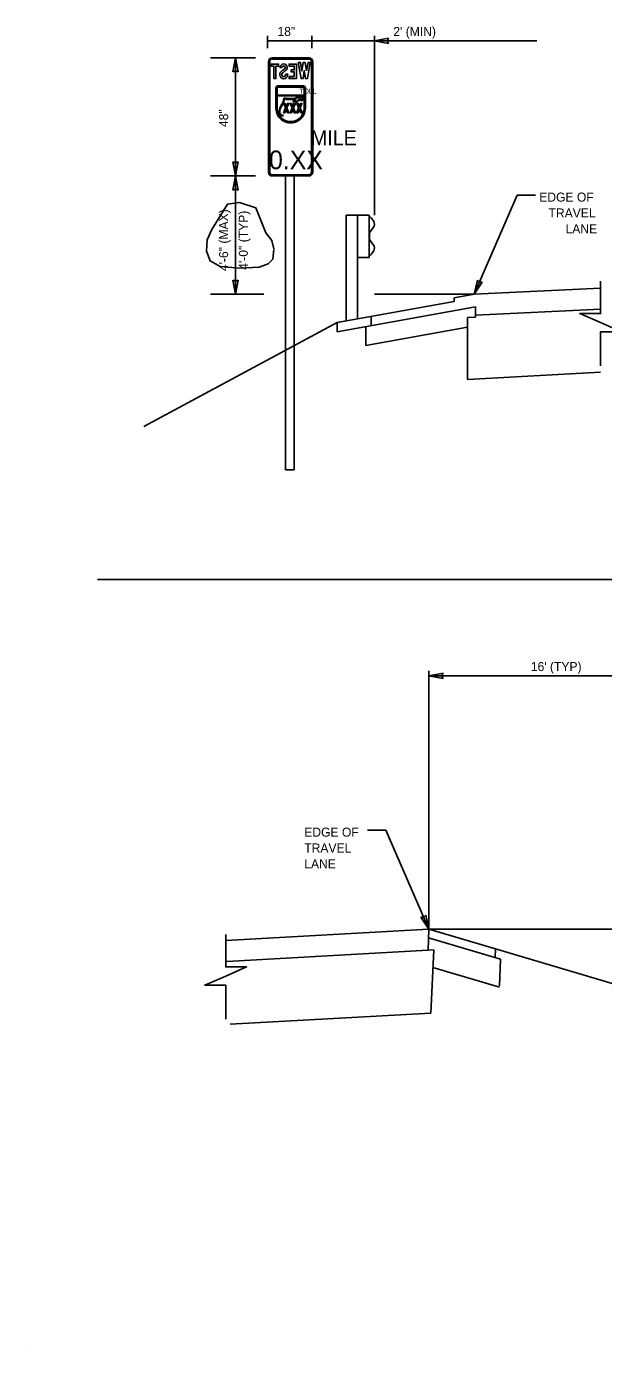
# Model space of a CAD drawing. Extents: x 56768 to 57406, y 11696 to 12105.
# Drawn here: x 56767.9 to 56946.4, y 11696.3 to 12105.2 of the extents above; entities that cross this region are included whole.
import ezdxf

# ---------------------------------------------------------------- set-up
doc = ezdxf.new("R2010")
doc.units = 0
for name, color, linetype in [('1', 7, 'Continuous'), ('52', 7, 'Continuous'), ('62', 7, 'Continuous'), ('AdhocPoint_dp', 7, 'Continuous'), ('Default', 7, 'Continuous'), ('DimLines_dp', 7, 'Continuous'), ('SheetBorder_dp', 7, 'Continuous'), ('SignPanel', 7, 'Continuous'), ('XSGrdLine_ex', 7, 'Continuous')]:
    doc.layers.add(name, color=color, linetype=linetype)

msp = doc.modelspace()

# ---------------------------------------------------------------- linework, layer by layer
at = {"layer": '1'}
for p, q in [((56848.03, 12005.09), (56848.03, 12058.97)), ((56850.69, 12006.52), (56850.69, 12058.97)), ((56848.03, 11968.2), (56848.03, 12005.09)), ((56850.69, 11968.2), (56850.69, 12006.52)), ((56850.69, 11968.2), (56848.03, 11968.2))]:
    msp.add_line(p, q, dxfattribs=at)
at = {"layer": '52'}
for p, q in [((56824.81, 12022.47), (56841.31, 12022.47)), ((56875.53, 12022.47), (56906.41, 12022.47)), ((56970.53, 11826.22), (56892.41, 11826.22))]:
    msp.add_line(p, q, dxfattribs=at)
at = {"layer": '62'}
msp.add_lwpolyline([(56844.47, 12036.41), (56843.77, 12039.01), (56841.97, 12041.42), (56838.86, 12049.17), (56833.76, 12050.77), (56830.06, 12050.27), (56825.26, 12042.42), (56823.76, 12039.21), (56823.56, 12035.71), (56824.76, 12032.7), (56827.86, 12031), (56833.76, 12030.5), (56839.86, 12030.8), (56842.67, 12031.8), (56844.07, 12033.31), (56844.47, 12036.21)], dxfattribs=at)
at = {"layer": 'AdhocPoint_dp'}
msp.add_line((56767.89, 11696.32), (56767.89, 11696.32), dxfattribs=at)
at = {"layer": 'Default'}
for points in [[(56945.5, 12000.28), (56945.5, 12010.84), (56951.96, 12010.84), (56945.5, 12013.65), (56939.04, 12016.47), (56945.5, 12016.47), (56945.5, 12026.47)], [(56829.53, 11798.37), (56829.53, 11808.93), (56823.07, 11808.93), (56829.53, 11811.74), (56835.99, 11814.56), (56829.53, 11814.56), (56829.53, 11824.56)]]:
    msp.add_lwpolyline(points, dxfattribs=at)
at = {"layer": 'DimLines_dp'}
for p, q in [((56842.51, 12098.47), (56842.51, 12102.3)), ((56856.2, 12098.47), (56856.2, 12102.3)), ((56875.53, 12046.89), (56875.53, 12102.3)), ((56856.2, 12100.75), (56842.51, 12100.75)), ((56856.2, 12100.75), (56925.74, 12100.75)), ((56875.53, 12100.75), (56879.88, 12101.59)), ((56879.88, 12099.94), (56875.53, 12100.75)), ((56879.88, 12101.59), (56879.55, 12100.75)), ((56879.55, 12100.75), (56879.88, 12099.94)), ((56824.81, 12095.47), (56838.74, 12095.47)), ((56831.74, 12091.12), (56832.55, 12095.47)), ((56832.55, 12095.47), (56832.55, 12058.97)), ((56832.55, 12095.47), (56833.39, 12091.12)), ((56832.55, 12091.45), (56831.74, 12091.12)), ((56833.39, 12091.12), (56832.55, 12091.45)), ((56832.55, 12058.97), (56831.71, 12063.32)), ((56831.71, 12063.32), (56832.55, 12062.99)), ((56832.55, 12058.97), (56831.71, 12063.32)), ((56831.71, 12063.32), (56832.55, 12062.99)), ((56832.55, 12062.99), (56833.36, 12063.32)), ((56833.36, 12063.32), (56832.55, 12058.97)), ((56832.55, 12062.99), (56833.36, 12063.32)), ((56833.36, 12063.32), (56832.55, 12058.97)), ((56824.81, 12058.97), (56838.74, 12058.97)), ((56831.74, 12054.62), (56832.55, 12058.97)), ((56832.55, 12058.97), (56832.55, 12022.47)), ((56832.55, 12058.97), (56833.39, 12054.62)), ((56832.55, 12054.95), (56831.74, 12054.62)), ((56833.39, 12054.62), (56832.55, 12054.95)), ((56919.73, 12053.08), (56906.41, 12022.46)), ((56925.38, 12053.08), (56919.73, 12053.08)), ((56832.55, 12022.47), (56831.71, 12026.82)), ((56831.71, 12026.82), (56832.55, 12026.49)), ((56832.55, 12026.49), (56833.36, 12026.82)), ((56833.36, 12026.82), (56832.55, 12022.47)), ((56906.41, 12022.46), (56907.37, 12026.79)), ((56908.89, 12026.13), (56906.41, 12022.46)), ((56907.37, 12026.79), (56908.01, 12026.15)), ((56908.01, 12026.15), (56908.89, 12026.13)), ((56892.41, 11826.22), (56892.41, 11906.05)), ((56896.76, 11905.31), (56892.41, 11904.5)), ((56892.41, 11904.5), (56896.76, 11903.66)), ((56973.53, 11904.5), (56892.41, 11904.5)), ((56896.43, 11904.5), (56896.76, 11905.31)), ((56896.76, 11903.66), (56896.43, 11904.5)), ((56873.44, 11856.84), (56879.09, 11856.84)), ((56879.09, 11856.84), (56892.41, 11826.22)), ((56890.8, 11829.91), (56889.93, 11829.89)), ((56889.93, 11829.89), (56892.41, 11826.22)), ((56891.44, 11830.55), (56890.8, 11829.91)), ((56892.41, 11826.22), (56891.44, 11830.55))]:
    msp.add_line(p, q, dxfattribs=at)
at = {"layer": 'SheetBorder_dp'}
msp.add_line((57405.89, 11934.25), (56789.89, 11934.25), dxfattribs=at)
at = {"layer": 'SignPanel'}
for p, q in [((56846.91, 12092.46), (56846.3, 12092.46)), ((56846.91, 12092.46), (56846.3, 12092.46)), ((56846.91, 12092.46), (56846.3, 12092.46)), ((56848.11, 12090.45), (56848.73, 12090.45)), ((56848.11, 12090.45), (56848.73, 12090.45)), ((56848.11, 12090.45), (56848.73, 12090.45)), ((56845.04, 12079.95), (56845.04, 12086.23)), ((56845.24, 12079.95), (56845.24, 12086.23)), ((56845.43, 12083.95), (56845.43, 12086.23)), ((56853.6, 12086.8), (56845.61, 12086.8)), ((56853.6, 12086.61), (56845.61, 12086.61)), ((56853.6, 12086.42), (56845.61, 12086.42)), ((56853.79, 12083.95), (56853.79, 12086.23)), ((56853.98, 12079.95), (56853.98, 12086.23)), ((56854.17, 12079.95), (56854.17, 12086.23)), ((56853.79, 12083.95), (56845.43, 12083.95)), ((56845.43, 12079.95), (56845.43, 12083.76)), ((56853.79, 12083.76), (56845.43, 12083.76)), ((56847.49, 12083.02), (56847.16, 12081.58)), ((56847.38, 12081.5), (56847.68, 12082.79)), ((56848.23, 12083.02), (56847.49, 12083.02)), ((56847.68, 12082.79), (56848.11, 12082.79)), ((56848.11, 12082.79), (56848.21, 12082.63)), ((56848.21, 12082.63), (56851.22, 12082.63)), ((56848.33, 12082.86), (56848.23, 12083.02)), ((56851.06, 12082.86), (56848.33, 12082.86)), ((56850.77, 12082.34), (56850.27, 12082)), ((56850.27, 12082), (56850.4, 12081.81)), ((56850.4, 12081.81), (56850.77, 12082.07)), ((56851.38, 12081.98), (56850.77, 12082.34)), ((56850.77, 12082.07), (56851.41, 12081.7)), ((56851.19, 12083.21), (56851.06, 12082.86)), ((56853.57, 12083.39), (56851.19, 12083.21)), ((56851.22, 12082.63), (56851.36, 12082.99)), ((56851.36, 12082.99), (56853.3, 12083.14)), ((56851.83, 12082.4), (56851.38, 12081.98)), ((56851.41, 12081.7), (56851.95, 12082.19)), ((56852.75, 12082.7), (56851.83, 12082.4)), ((56851.95, 12082.19), (56852.7, 12082.44)), ((56852.32, 12083.05), (56852.32, 12083.05)), ((56852.7, 12082.44), (56852.95, 12082.24)), ((56853.02, 12082.48), (56852.75, 12082.7)), ((56852.95, 12082.24), (56853.41, 12082.3)), ((56853.2, 12082.51), (56853.02, 12082.48)), ((56853.3, 12083.14), (56853.2, 12082.51)), ((56853.41, 12082.3), (56853.57, 12083.39)), ((56853.79, 12079.95), (56853.79, 12083.76)), ((56846.3, 12080), (56846.05, 12079.08)), ((56846.05, 12079.08), (56846.05, 12078.21)), ((56846.05, 12078.21), (56846.8, 12077.6)), ((56846.28, 12079.05), (56846.51, 12079.91)), ((56846.28, 12078.32), (56846.28, 12079.05)), ((56846.9, 12077.81), (56846.28, 12078.32)), ((56846.71, 12080.67), (56846.3, 12080)), ((56846.51, 12079.91), (56846.94, 12080.61)), ((56847.16, 12081.58), (56846.71, 12080.86)), ((56846.71, 12080.86), (56846.71, 12080.67)), ((56846.8, 12077.6), (56847.16, 12077.51)), ((56847.11, 12077.76), (56846.9, 12077.81)), ((56846.94, 12080.79), (56847.38, 12081.5)), ((56846.94, 12080.61), (56846.94, 12080.79)), ((56847.25, 12077.86), (56847.11, 12077.76)), ((56847.16, 12077.51), (56847.38, 12077.67)), ((56847.38, 12077.67), (56847.25, 12077.86))]:
    msp.add_line(p, q, dxfattribs=at)
for points in [[(56842.76, 12094.33), (56842.76, 12060.11)], [(56843.14, 12094.33), (56843.14, 12060.11)], [(56855.31, 12095.47), (56843.9, 12095.47)], [(56855.31, 12095.09), (56843.9, 12095.09)], [(56856.07, 12060.11), (56856.07, 12094.33)], [(56856.45, 12060.11), (56856.45, 12094.33)], [(56843.9, 12059.35), (56855.31, 12059.35)], [(56843.9, 12058.97), (56855.31, 12058.97)]]:
    msp.add_lwpolyline(points, dxfattribs=at)
for points in [[(56854.54, 12091.43), (56854.14, 12093.99), (56853.53, 12093.99), (56853.13, 12091.43), (56852.68, 12093.99), (56851.98, 12093.99), (56852.86, 12089.04), (56853.45, 12089.04), (56853.84, 12091.52), (56854.23, 12089.04), (56854.81, 12089.04), (56855.69, 12093.99), (56855, 12093.99)], [(56854.54, 12091.43), (56854.14, 12093.99), (56853.53, 12093.99), (56853.13, 12091.43), (56852.68, 12093.99), (56851.98, 12093.99), (56852.86, 12089.04), (56853.45, 12089.04), (56853.84, 12091.52), (56854.23, 12089.04), (56854.81, 12089.04), (56855.69, 12093.99), (56855, 12093.99)], [(56854.54, 12091.43), (56854.14, 12093.99), (56853.53, 12093.99), (56853.13, 12091.43), (56852.68, 12093.99), (56851.98, 12093.99), (56852.86, 12089.04), (56853.45, 12089.04), (56853.84, 12091.52), (56854.23, 12089.04), (56854.81, 12089.04), (56855.69, 12093.99), (56855, 12093.99)], [(56845.05, 12092.91), (56845.87, 12092.91), (56845.87, 12093.54), (56843.61, 12093.54), (56843.61, 12092.91), (56844.43, 12092.91), (56844.43, 12089.04), (56845.05, 12089.04)], [(56845.05, 12092.91), (56845.87, 12092.91), (56845.87, 12093.54), (56843.61, 12093.54), (56843.61, 12092.91), (56844.43, 12092.91), (56844.43, 12089.04), (56845.05, 12089.04)], [(56845.05, 12092.91), (56845.87, 12092.91), (56845.87, 12093.54), (56843.61, 12093.54), (56843.61, 12092.91), (56844.43, 12092.91), (56844.43, 12089.04), (56845.05, 12089.04)], [(56850.76, 12089.67), (56850.76, 12091.11), (56849.79, 12091.11), (56849.79, 12091.74), (56850.76, 12091.74), (56850.76, 12092.91), (56849.12, 12092.91), (56849.12, 12093.54), (56851.38, 12093.54), (56851.38, 12089.04), (56849.12, 12089.04), (56849.12, 12089.67)], [(56850.76, 12089.67), (56850.76, 12091.11), (56849.79, 12091.11), (56849.79, 12091.74), (56850.76, 12091.74), (56850.76, 12092.91), (56849.12, 12092.91), (56849.12, 12093.54), (56851.38, 12093.54), (56851.38, 12089.04), (56849.12, 12089.04), (56849.12, 12089.67)], [(56850.76, 12089.67), (56850.76, 12091.11), (56849.79, 12091.11), (56849.79, 12091.74), (56850.76, 12091.74), (56850.76, 12092.91), (56849.12, 12092.91), (56849.12, 12093.54), (56851.38, 12093.54), (56851.38, 12089.04), (56849.12, 12089.04), (56849.12, 12089.67)], [(56848.69, 12078.53), (56848.28, 12079.51), (56847.87, 12078.53), (56847.44, 12078.53), (56848.06, 12080.02), (56847.49, 12081.39), (56847.92, 12081.39), (56848.28, 12080.53), (56848.64, 12081.39), (56849.06, 12081.39), (56848.49, 12080.02), (56849.11, 12078.53)], [(56850.7, 12078.53), (56850.29, 12079.51), (56849.88, 12078.53), (56849.46, 12078.53), (56850.08, 12080.02), (56849.51, 12081.39), (56849.93, 12081.39), (56850.29, 12080.53), (56850.65, 12081.39), (56851.08, 12081.39), (56850.51, 12080.02), (56851.13, 12078.53)], [(56852.72, 12078.53), (56852.31, 12079.51), (56851.9, 12078.53), (56851.47, 12078.53), (56852.1, 12080.02), (56851.52, 12081.39), (56851.95, 12081.39), (56852.31, 12080.53), (56852.67, 12081.39), (56853.09, 12081.39), (56852.52, 12080.02), (56853.14, 12078.53)]]:
    msp.add_lwpolyline(points, close=True, dxfattribs=at)
for centre, radius, start, end in [((56843.9, 12094.33), 1.14, 90, 180), ((56843.9, 12094.33), 0.76, 90, 180), ((56855.31, 12094.33), 1.14, 0, 90), ((56855.31, 12094.33), 0.76, 0, 90), ((56843.9, 12060.11), 1.14, 180, 270), ((56843.9, 12060.11), 0.76, 180, 270), ((56855.31, 12060.11), 1.14, 270, 0), ((56855.31, 12060.11), 0.76, 270, 0)]:
    msp.add_arc(centre, radius, start, end, dxfattribs=at)
for centre, major_axis, ratio, start_param, end_param in [((56847.64, 12090.27), (0, -1.4), 0.981197, 3.939023, 5.163791), ((56847.64, 12090.27), (0, -1.4), 0.981197, 3.939023, 5.163791), ((56847.64, 12090.27), (0, -1.4), 0.981197, 3.939023, 5.163791), ((56847.45, 12092.43), (0, -1.17), 0.981197, 1.634182, 4.688511), ((56847.45, 12092.43), (0, -1.17), 0.981197, 1.634182, 4.688511), ((56847.45, 12092.43), (0, -1.17), 0.981197, 1.634182, 4.688511), ((56849.76, 12088.29), (0, -4.32), 0.981197, 3.642536, 3.961892), ((56849.76, 12088.29), (0, -4.32), 0.981197, 3.642536, 3.961892), ((56849.76, 12088.29), (0, -4.32), 0.981197, 3.642536, 3.961892), ((56847.65, 12090.27), (0, -0.78), 0.981197, 3.79238, 5.170369), ((56847.65, 12090.27), (0, -0.78), 0.981197, 3.79238, 5.170369), ((56847.65, 12090.27), (0, -0.78), 0.981197, 3.79238, 5.170369), ((56847.45, 12092.42), (0, -0.55), 0.981197, 2.28404, 4.637874), ((56847.45, 12092.42), (0, -0.55), 0.981197, 2.28404, 4.637874), ((56847.45, 12092.42), (0, -0.55), 0.981197, 2.28404, 4.637874), ((56847.46, 12090.19), (0, -0.572), 0.981197, 5.194718, 7.162991), ((56847.46, 12090.19), (0, -0.572), 0.981197, 5.194718, 7.162991), ((56847.46, 12090.19), (0, -0.572), 0.981197, 5.194718, 7.162991), ((56850.3, 12087.61), (0, -4.56), 0.981197, 3.63779, 3.909641), ((56850.3, 12087.61), (0, -4.56), 0.981197, 3.63779, 3.909641), ((56850.3, 12087.61), (0, -4.56), 0.981197, 3.63779, 3.909641), ((56847.52, 12092.49), (0, -0.453), 0.981197, 0.484634, 2.267813), ((56847.52, 12092.49), (0, -0.453), 0.981197, 0.484634, 2.267813), ((56847.52, 12092.49), (0, -0.453), 0.981197, 0.484634, 2.267813), ((56847.23, 12090.41), (0, -0.897), 0.981197, 0.859453, 1.616836), ((56847.29, 12090.39), (0, -1.47), 0.981197, 0.439911, 1.615229), ((56847.23, 12090.41), (0, -0.897), 0.981197, 0.859453, 1.616836), ((56847.29, 12090.39), (0, -1.47), 0.981197, 0.439911, 1.615229), ((56847.23, 12090.41), (0, -0.897), 0.981197, 0.859453, 1.616836), ((56847.29, 12090.39), (0, -1.47), 0.981197, 0.439911, 1.615229), ((56847.56, 12092.47), (0, -1.05), 0.981197, 0.629826, 1.606762), ((56847.56, 12092.47), (0, -1.05), 0.981197, 0.629826, 1.606762), ((56847.56, 12092.47), (0, -1.05), 0.981197, 0.629826, 1.606762), ((56845.62, 12086.23), (0, 0.57), 0.9997, 0, 1.570796), ((56845.62, 12086.23), (0, 0.38), 0.9997, 0, 1.570796), ((56845.62, 12086.23), (0, 0.19), 0.9997, 0, 1.570796), ((56847.49, 12090.2), (0, -1.23), 0.981197, 5.173086, 6.638731), ((56847.49, 12090.2), (0, -1.23), 0.981197, 5.173086, 6.638731), ((56847.49, 12090.2), (0, -1.23), 0.981197, 5.173086, 6.638731), ((56853.6, 12086.23), (0, 0.57), 0.9997, 4.712389, 6.283185), ((56853.6, 12086.23), (0, 0.38), 0.9997, 4.712389, 6.283185), ((56853.6, 12086.23), (0, 0.19), 0.9997, 4.712389, 6.283185), ((56849.61, 12079.95), (0, 4.56), 0.9997, 1.570796, 4.712389), ((56849.61, 12079.95), (0, 4.37), 0.9997, 1.570796, 4.712389), ((56849.61, 12079.95), (0, 4.18), 0.9997, 1.570796, 4.712389)]:
    msp.add_ellipse(centre, major_axis=major_axis, ratio=ratio, start_param=start_param, end_param=end_param, dxfattribs=at)
at = {"layer": 'XSGrdLine_ex'}
for p, q in [((56866.81, 12014.16), (56866.81, 12046.89)), ((56866.81, 12046.89), (56873.91, 12046.89)), ((56870.3, 12014.79), (56870.3, 12046.89)), ((56873.91, 12033.81), (56873.91, 12046.89)), ((56873.92, 12046.32), (56874.39, 12046.1)), ((56874.62, 12045.89), (56875.31, 12044.85)), ((56873.99, 12040.92), (56873.99, 12039.81)), ((56874.21, 12041.73), (56875.28, 12043.14)), ((56874.21, 12039.02), (56875.28, 12037.61)), ((56870.3, 12033.81), (56873.91, 12033.81)), ((56873.92, 12034.41), (56874.39, 12034.62)), ((56874.62, 12034.86), (56875.31, 12035.88)), ((56906.41, 12022.46), (56900.25, 12021.36)), ((56900.25, 12021.36), (56900.25, 12020.18)), ((56900.25, 12020.18), (56863.97, 12013.65)), ((56863.97, 12010.81), (56906.82, 12018.53)), ((56906.82, 12018.53), (56906.82, 12015.37)), ((56863.97, 12013.65), (56804.25, 11981.59)), ((56863.97, 12013.65), (56863.97, 12010.81)), ((56872.83, 12012.41), (56872.83, 12006.59)), ((56904.35, 12012.26), (56872.83, 12006.59)), ((56874.53, 12015.55), (56874.53, 12012.71)), ((56906.82, 12015.37), (56904.35, 12015.22)), ((56904.35, 12015.22), (56904.35, 11996.05)), ((56945.5, 11998.32), (56904.35, 11996.05)), ((56892.41, 11826.22), (56829.53, 11822.74)), ((56892.12, 11819.71), (56892.41, 11826.22)), ((56892.41, 11826.22), (56913.04, 11820.09)), ((56892.29, 11823.55), (56914.58, 11816.92)), ((56913.04, 11820.09), (56912.93, 11817.42)), ((56978.01, 11800.77), (56913.04, 11820.09)), ((56829.88, 11816.26), (56892.12, 11819.71)), ((56893.87, 11819.8), (56892.12, 11819.71)), ((56893, 11800.26), (56893.87, 11819.8)), ((56914.58, 11816.92), (56914.21, 11808.7)), ((56893.63, 11814.4), (56914.19, 11808.28)), ((56893, 11800.26), (56830.96, 11796.82))]:
    msp.add_line(p, q, dxfattribs=at)
for points in [[(56945.5, 12024.32), (56906.41, 12022.46)], [(56945.5, 12017.82), (56906.82, 12015.99)]]:
    msp.add_lwpolyline(points, dxfattribs=at)
for centre, major_axis, start_param, end_param in [((56874.24, 12044.85), (0, 1.28), 5.646537, 6.041895), ((56875, 12044.01), (0, -1.05), 0.577206, 2.505315), ((56874.48, 12040.9), (0, -0.976), 3.718758, 4.701029), ((56874.48, 12039.82), (0, -0.976), 4.723749, 5.70602), ((56875, 12036.72), (0, 1.05), 3.777871, 5.70598), ((56874.24, 12035.88), (0, -1.28), 0.24129, 0.636649)]:
    msp.add_ellipse(centre, major_axis=major_axis, ratio=0.5, start_param=start_param, end_param=end_param, dxfattribs=at)

# ---------------------------------------------------------------- texts
at = {"layer": 'DimLines_dp'}
for s, p in [('18"', (56845.55, 12102.22)), ("2' (MIN)", (56881.38, 12102.22)), ('EDGE OF ', (56926.52, 12051.04)), ('TRAVEL ', (56929.39, 12046.14)), ('LANE', (56934.65, 12041.24)), ("16' (TYP)", (56923.92, 11905.97)), ('EDGE OF ', (56853.83, 11854.8)), ('TRAVEL ', (56853.83, 11849.9)), ('LANE', (56853.83, 11845))]:
    msp.add_text(s, height=2.8, dxfattribs=at).set_placement(p)
for s, p in [('48"', (56830.29, 12074.08)), ('4\'-6" (MAX)', (56830.29, 12029.57)), ('4\'-0" (TYP)', (56836.38, 12029.97))]:
    msp.add_text(s, height=2.8, rotation=90, dxfattribs=at).set_placement(p)
at = {"layer": 'SignPanel'}
for s, height, p in [('TOLL', 1.519, (56852.36, 12084.42)), ('MILE', 4.562, (56855.86, 12068.47))]:
    msp.add_text(s, height=height, dxfattribs=at).set_placement(p)
msp.add_text('0.XX', height=5.75, rotation=360, dxfattribs=at).set_placement((56842.93, 12061.07))

doc.saveas('drawing.dxf')
